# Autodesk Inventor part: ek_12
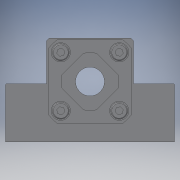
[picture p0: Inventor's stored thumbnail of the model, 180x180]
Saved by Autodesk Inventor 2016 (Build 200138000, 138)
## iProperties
Company: TraceParts S.A.
Created: 2017-01
Part Number: ek_12
Checked By: TraceParts S.A.
Catalog Web Link: www.traceparts.com
Document SubType Name: Modeling
Designer: TraceParts
Material: Типовые
Density: 1 g/cm^3
Appearance: По умолчанию
REFERENCE: EK 12
DESIGN: Фиксированная опора EK
SUPPLIER: Technische Antriebselemente GmbH - Germany
TraceParts.PartNumber: 80-08072009-803346
TraceParts.PartTitle: Фиксированная опора EK
TraceParts.InstanceId: 80-08072009-80334624VIC13JVL1GTFSGJTU4BBXLS
TraceParts.PartStatus: Published
TraceParts.PartVersion: 1.0.9
TRACEPARTS: TRACEPARTS
TraceParts.PartLanguage: ru
TraceParts.ClassPath: TEA_GER:/TEA_GER.1/TEA.120/TEA.120.020/80-08072009-803346
Author: TraceParts
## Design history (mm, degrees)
feature "ek_12"
node "Твердое тело1"
node "Твердые тела"
node "Поверхностные тела"
